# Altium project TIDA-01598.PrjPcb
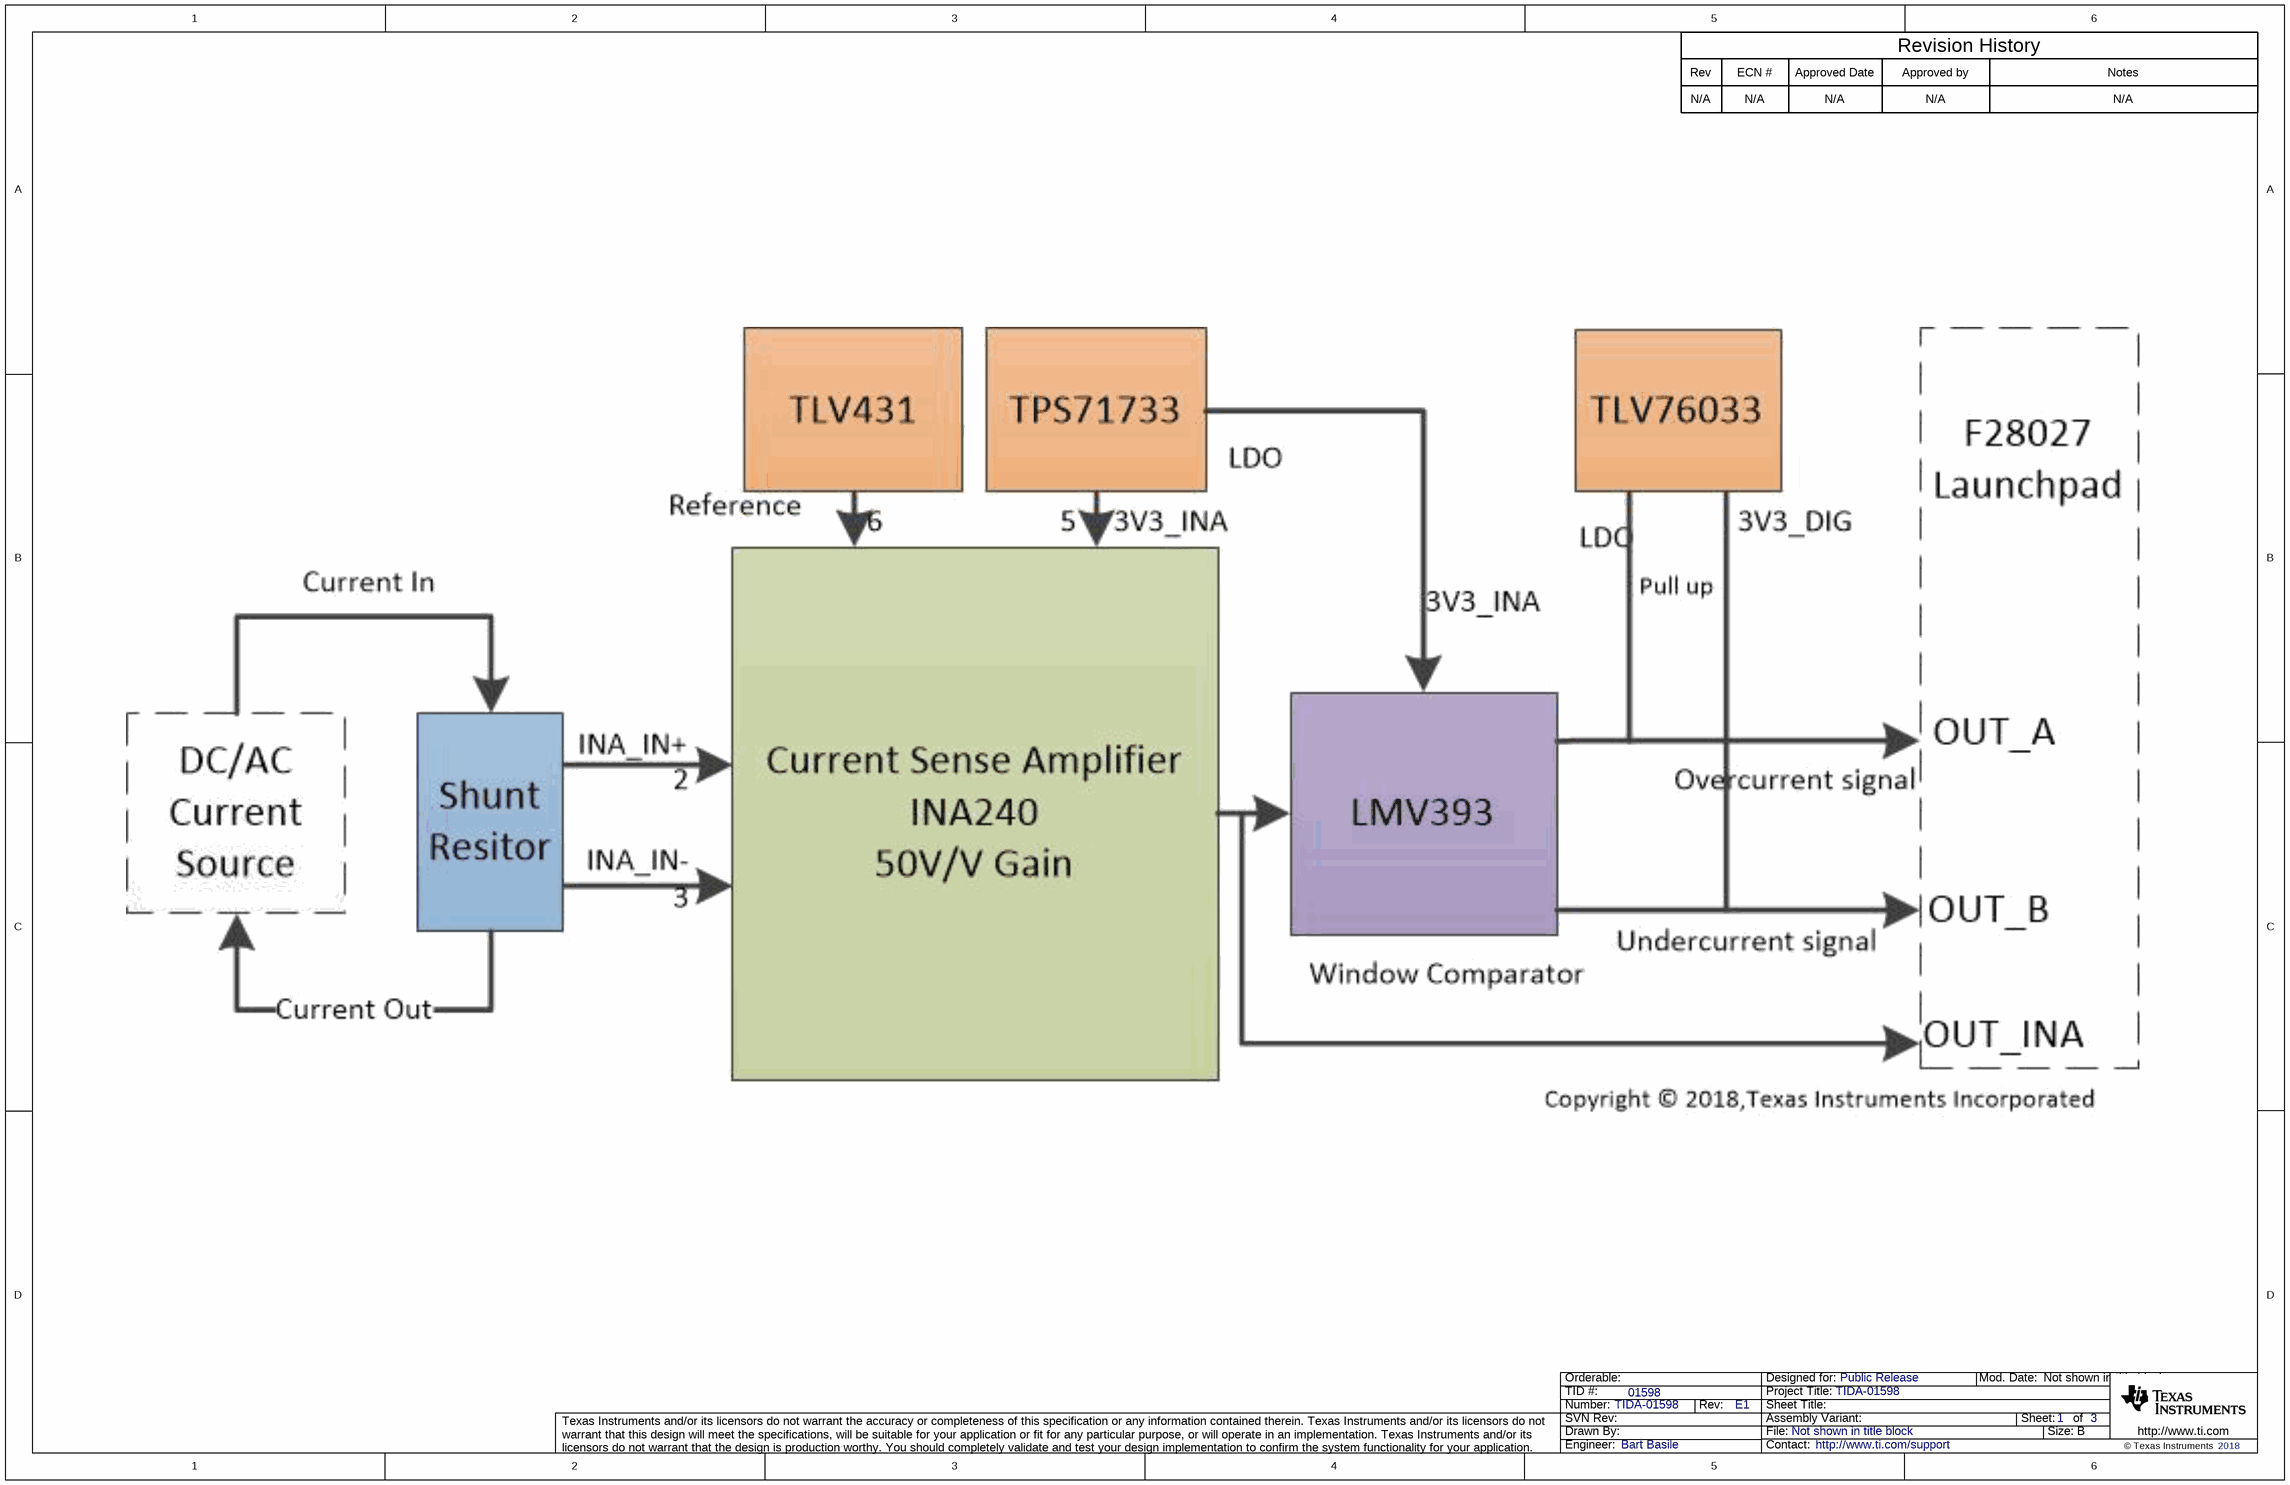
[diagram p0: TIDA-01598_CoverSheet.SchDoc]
CopyrightYear: 2018; PCB_Layout: Avinash N; PCB_Rev: E1; PRJ_Customer: Public Release; PRJ_Engineer: Bart Basile; PRJ_Number: TIDA-01598; PRJ_Title: TIDA-01598; SCH_Rev: E1; TechSupport: http://www.ti.com/support; TID: 01598
4 sheets, 100 parts. Net scope: global (net labels, ports and power ports of the same name join across sheets).
Board file: TIDA-01598_PCB.PcbDoc
Sheets:
  TIDA-01598_CoverSheet.SchDoc
  TIDA-01598_BlankSheet.SchDoc
  TIDA-01598_Main.SchDoc
  TIDA-01598_EVM_Hardware.SchDoc

## Sheet TIDA-01598_CoverSheet.SchDoc
size 431 x 279 mm; Date: Not shown in title block; ApprovedBy: Not shown in title block; CheckedBy: Not shown in title block; Author: Not shown in title block; CompanyName: Not shown in title block; Engineer: Not shown in title block; Organization: Not shown in title block; Address1: Not shown in title block; Address2: Not shown in title block; Address3: Not shown in title block; Address4: Not shown in title block; DocumentNumber: 1; Revision: Use project parameter SCH_Rev; SheetNumber: 1; SheetTotal: 3; PageSetup: Record=PageOptions¦CenterHorizontal=True¦CenterVertical=True¦PrintScale=1.00¦XCorrection=1.00¦YCorrection=1.00¦PrintKind=0¦BorderSize=5000000¦LeftOffset=0¦BottomOffset=0¦Orientation=2¦PaperLength=1000¦PaperWidth=1000¦Scale=100¦PaperSource=15¦PrintQuality=600¦MediaType=1¦DitherType=10¦PaperKind=Letter¦PrintScaleMode=1

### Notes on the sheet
- Rev
- N/A
- ECN #
- Approved Date
- Approved by
- Revision History
- Notes

## Sheet TIDA-01598_BlankSheet.SchDoc
size 431 x 279 mm; Date: Not shown in title block; ApprovedBy: Not shown in title block; CheckedBy: Not shown in title block; Author: Not shown in title block; CompanyName: Not shown in title block; Engineer: Not shown in title block; Organization: Not shown in title block; Address1: Not shown in title block; Address2: Not shown in title block; Address3: Not shown in title block; Address4: Not shown in title block; DocumentNumber: 1; Revision: Use project parameter SCH_Rev; SheetNumber: 2; SheetTotal: 3; PageSetup: Record=PageOptions¦CenterHorizontal=True¦CenterVertical=True¦PrintScale=1.00¦XCorrection=1.00¦YCorrection=1.00¦PrintKind=0¦BorderSize=5000000¦LeftOffset=0¦BottomOffset=0¦Orientation=2¦PaperLength=1000¦PaperWidth=1000¦Scale=100¦PaperSource=15¦PrintQuality=600¦MediaType=1¦DitherType=10¦PaperKind=Letter¦PrintScaleMode=1

## Sheet TIDA-01598_Main.SchDoc
size 431 x 279 mm; Date: Not shown in title block; ApprovedBy: Not shown in title block; CheckedBy: Not shown in title block; Author: Not shown in title block; CompanyName: Not shown in title block; Engineer: Not shown in title block; Organization: Not shown in title block; Address1: Not shown in title block; Address2: Not shown in title block; Address3: Not shown in title block; Address4: Not shown in title block; DocumentNumber: 1; Revision: Use project parameter SCH_Rev; SheetNumber: 2; SheetTotal: 3; PageSetup: Record=PageOptions¦CenterHorizontal=True¦CenterVertical=True¦PrintScale=1.00¦XCorrection=1.00¦YCorrection=1.00¦PrintKind=0¦BorderSize=5000000¦LeftOffset=0¦BottomOffset=0¦Orientation=2¦PaperLength=1000¦PaperWidth=1000¦Scale=100¦PaperSource=15¦PrintQuality=600¦MediaType=1¦DitherType=10¦PaperKind=Letter¦PrintScaleMode=1
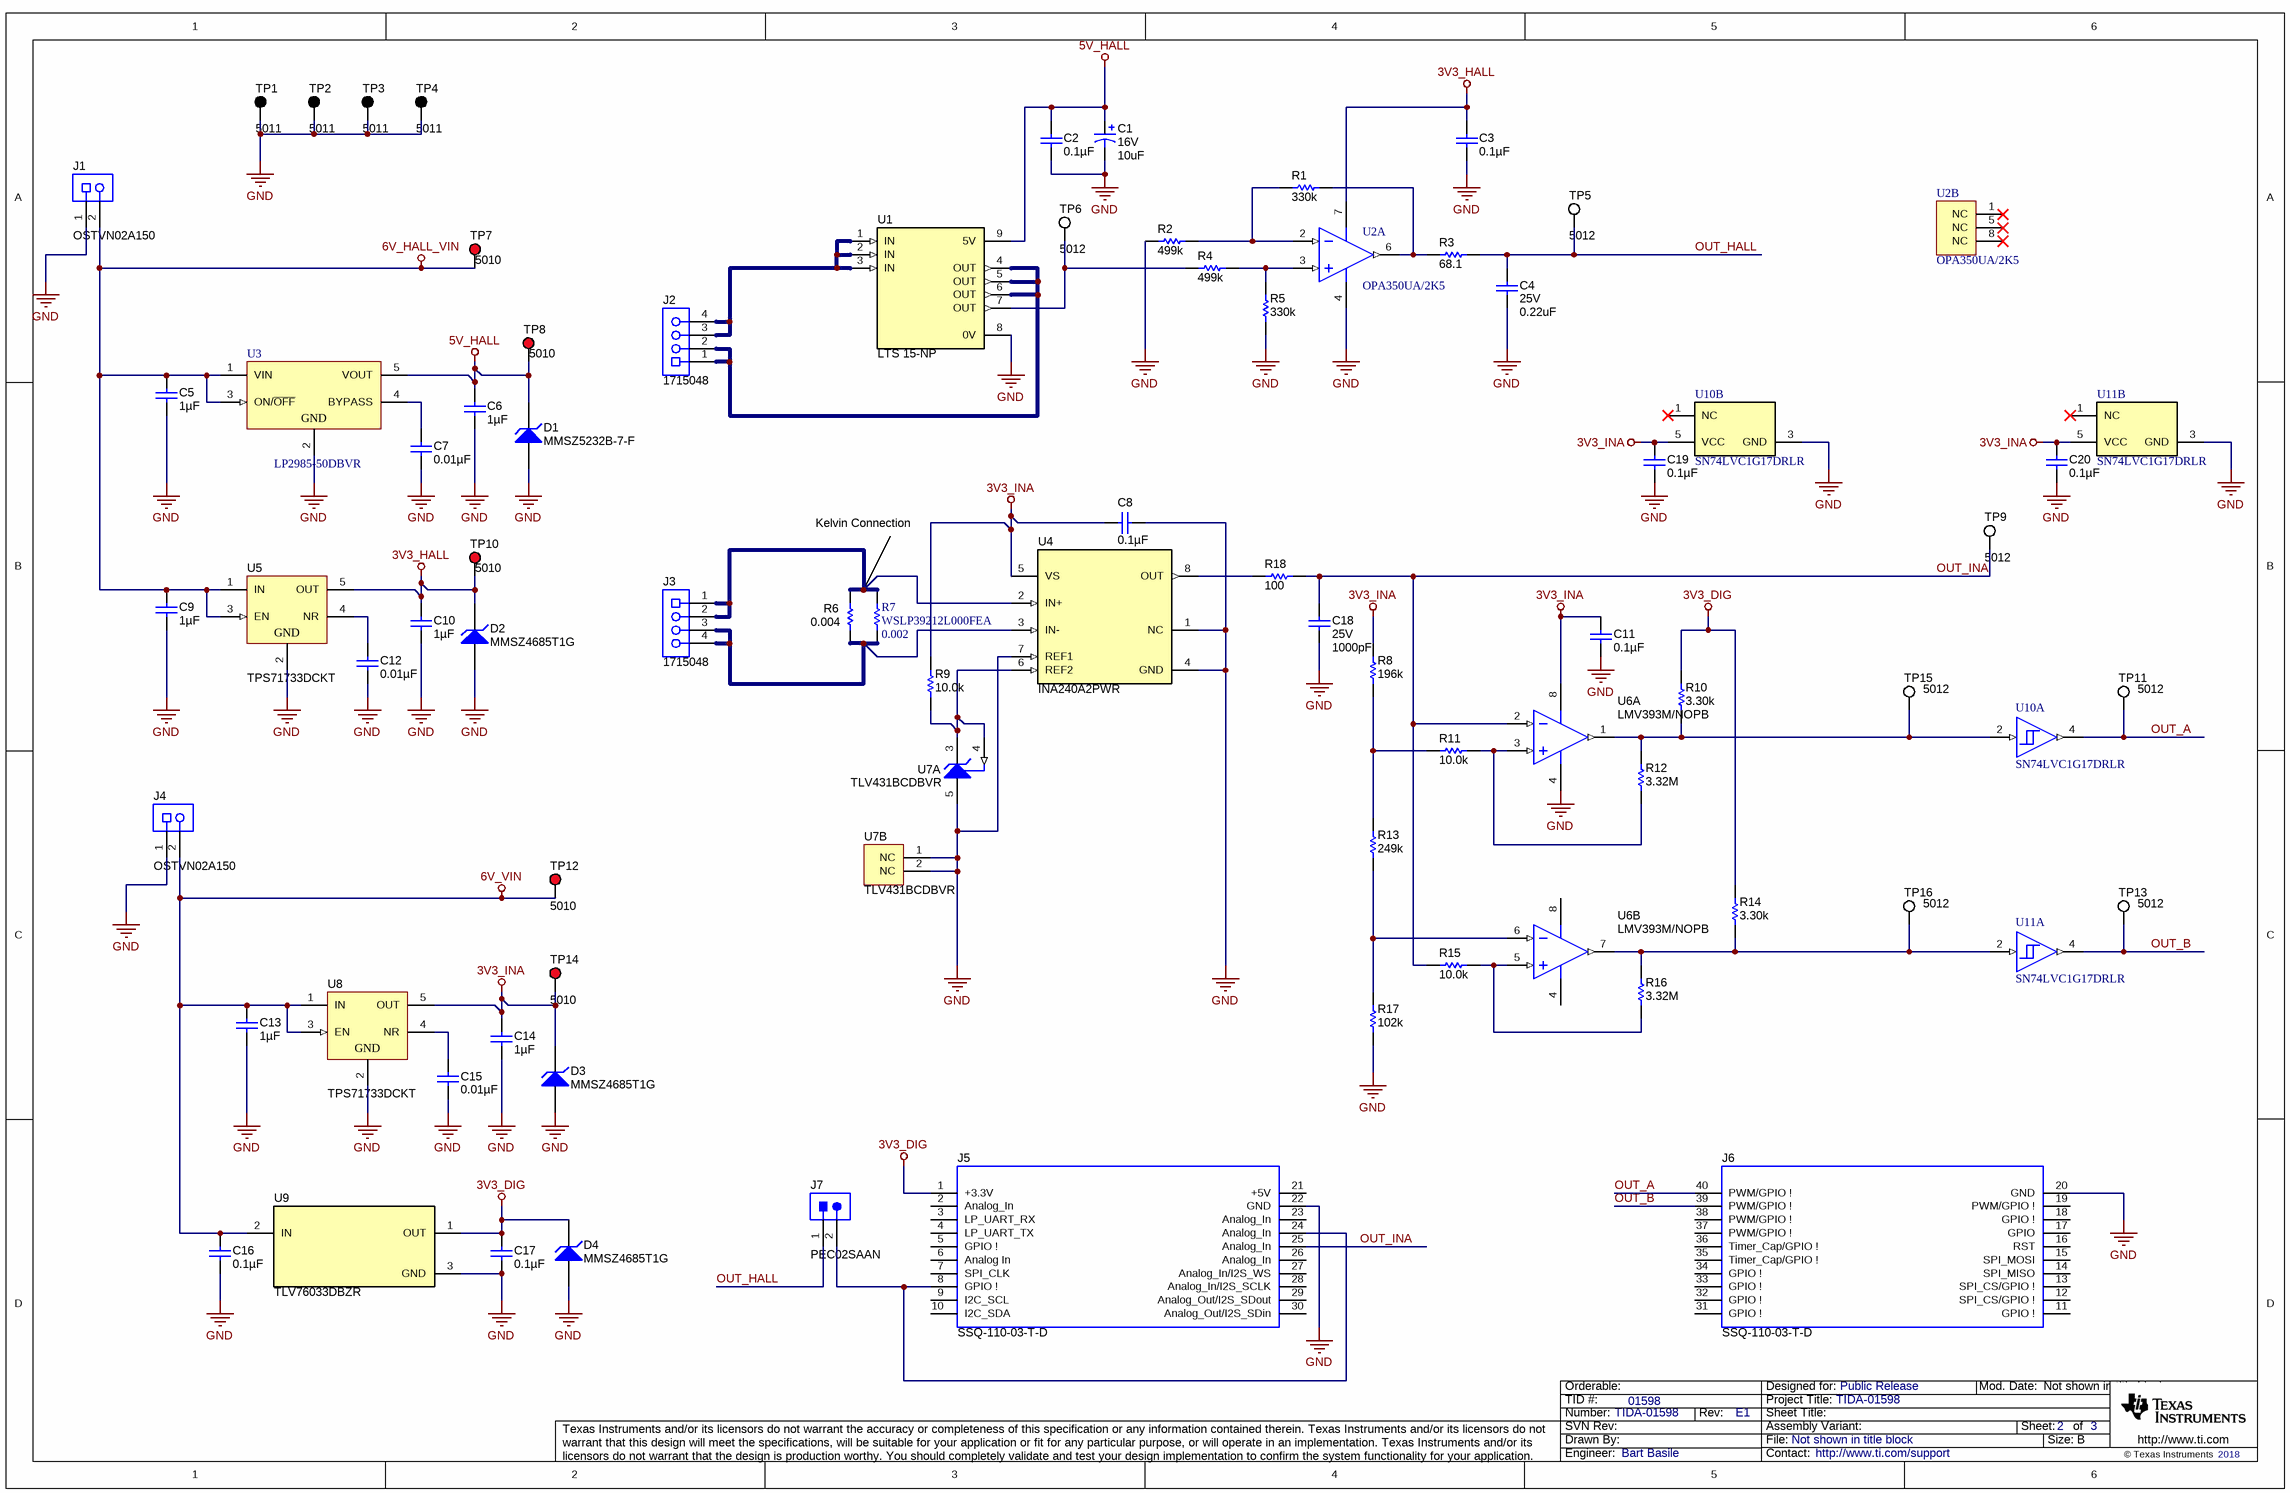
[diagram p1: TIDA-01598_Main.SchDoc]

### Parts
C1  VDC_V: 16V  ValueDisplayed: 10uF  [3528-21]  (hidden comment: TAJB106K016RNJ)
C2  ValueDisplayed: 0.1µF  [0805_HV]  (hidden comment: C0805C104K4RACTU)
C3  ValueDisplayed: 0.1µF  [0402]  (hidden comment: 885012205037)
C4  VDC_V: 25V  ValueDisplayed: 0.22uF  [0603]  (hidden comment: C0603C224J3RAC7867)
C5  ValueDisplayed: 1µF  [0402]  (hidden comment: C1005X5R1E105K050BC)
C6  ValueDisplayed: 1µF  [0402]  (hidden comment: C1005X5R1E105K050BC)
C7  ValueDisplayed: 0.01µF  [0402]  (hidden comment: GRM155R61A103KA01D)
C8  ValueDisplayed: 0.1µF  [0402]  (hidden comment: 885012205037)
C9  ValueDisplayed: 1µF  [0402]  (hidden comment: C1005X5R1E105K050BC)
C10  ValueDisplayed: 1µF  [0402]  (hidden comment: C1005X5R1E105K050BC)
C11  ValueDisplayed: 0.1µF  [0402]  (hidden comment: 885012205037)
C12  ValueDisplayed: 0.01µF  [0402]  (hidden comment: GRM155R61A103KA01D)
C13  ValueDisplayed: 1µF  [0402]  (hidden comment: C1005X5R1E105K050BC)
C14  ValueDisplayed: 1µF  [0402]  (hidden comment: C1005X5R1E105K050BC)
C15  ValueDisplayed: 0.01µF  [0402]  (hidden comment: GRM155R61A103KA01D)
C16  ValueDisplayed: 0.1µF  [0402]  (hidden comment: 885012205037)
C17  ValueDisplayed: 0.1µF  [0402]  (hidden comment: 885012205037)
C18  VDC_V: 25V  ValueDisplayed: 1000pF  [0402]  (hidden comment: C0402C102J3RACTU)
C19  ValueDisplayed: 0.1µF  [0402]  (hidden comment: 885012205037)
C20  ValueDisplayed: 0.1µF  [0402]  (hidden comment: 885012205037)
D1  MMSZ5232B-7-F  [SOD-123]
D2  MMSZ4685T1G  [SOD-123]
D3  MMSZ4685T1G  [SOD-123]
D4  MMSZ4685T1G  [SOD-123]
J1  OSTVN02A150  [On-Shore_OSTVN02A150]
J2  1715048  [Phoenix_1715048]
J3  1715048  [Phoenix_1715048]
J4  OSTVN02A150  [On-Shore_OSTVN02A150]
J5  SSQ-110-03-T-D  [BoosterPack_40pin_J1J3]
J6  SSQ-110-03-T-D  [BoosterPack_40pin_J2J4]
J7  PEC02SAAN  [CONN_PEC02SAAN]
R1  ValueDisplayed: 330k  [0603]  (hidden comment: ERJ-3EKF3303V)
R2  ValueDisplayed: 499k  [0603]  (hidden comment: ERJ-3EKF4993V)
R3  ValueDisplayed: 68.1  [0603]  (hidden comment: CRCW060368R1FKEA)
R4  ValueDisplayed: 499k  [0603]  (hidden comment: ERJ-3EKF4993V)
R5  ValueDisplayed: 330k  [0603]  (hidden comment: ERJ-3EKF3303V)
R6  ValueDisplayed: 0.004  [2010]  (hidden comment: PMR50HZPFV4L00)
R7  WSLP39212L000FEA  value 0.002  [RC3921]
R8  ValueDisplayed: 196k  [0603]  (hidden comment: RT0603BRD07196KL)
R9  ValueDisplayed: 10.0k  [0402]  (hidden comment: CRCW040210K0DHEDP)
R10  ValueDisplayed: 3.30k  [0402]  (hidden comment: ERJ-2RKF3301X)
R11  ValueDisplayed: 10.0k  [0402]  (hidden comment: CRCW040210K0DHEDP)
R12  ValueDisplayed: 3.32M  [0402]  (hidden comment: CRCW04023M32FKED)
R13  ValueDisplayed: 249k  [0603]  (hidden comment: RG1608P-2493-B-T5)
R14  ValueDisplayed: 3.30k  [0402]  (hidden comment: ERJ-2RKF3301X)
R15  ValueDisplayed: 10.0k  [0402]  (hidden comment: CRCW040210K0DHEDP)
R16  ValueDisplayed: 3.32M  [0402]  (hidden comment: CRCW04023M32FKED)
R17  ValueDisplayed: 102k  [0603]  (hidden comment: RT0603BRD07102KL)
R18  ValueDisplayed: 100  [0402]  (hidden comment: RC0402FR-07100RL)
TP1  5011  [Keystone5011]
TP2  5011  [Keystone5011]
TP3  5011  [Keystone5011]
TP4  5011  [Keystone5011]
TP5  5012  [Keystone5012]
TP6  5012  [Keystone5012]
TP7  5010  [Keystone5010]
TP8  5010  [Keystone5010]
TP9  5012  [Keystone5012]
TP10  5010  [Keystone5010]
TP11  5012  [Keystone5012]
TP12  5010  [Keystone5010]
TP13  5012  [Keystone5012]
TP14  5010  [Keystone5010]
TP15  5012  [Keystone5012]
TP16  5012  [Keystone5012]
U1  LTS 15-NP  [LEM_LTS]
U2  OPA350UA/2K5  [D0008A_L]  (parts A,B of 2)
U3  LP2985-50DBVR  [DBV0005A_N]
U4  INA240A2PWR  [PW0008A_L]
U5  TPS71733DCKT  [DCK0005A_N]
U6  LMV393M/NOPB  [D0008A_N]  (parts A,B of 2)
U7  TLV431BCDBVR  [DBV0005A_N]  (parts A,B of 2)
U8  TPS71733DCKT  [DCK0005A_N]
U9  TLV76033DBZR  [DBZ0003A_N]
U10  SN74LVC1G17DRLR  [DRL0005A]  (parts A,B of 2)
U11  SN74LVC1G17DRLR  [DRL0005A]  (parts A,B of 2)

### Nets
3V3_DIG: C17.1 D4.1(K) J5.1(+3.3V) R10.2 R14.2 U9.1(OUT)
3V3_HALL: C3.1 C10.1 D2.1(K) TP10.1 U2.7(V+) U5.5(OUT)
3V3_INA: C8.1 C11.1 C14.1 C19.1 C20.1 D3.1(K) R8.2 R9.2 TP14.1 U4.5(VS) U6.8(V+) U8.5(OUT) U10.5(VCC) U11.5(VCC)
5V_HALL: C1.1(+) C2.1 C6.1 D1.1(K) TP8.1 U1.9(5V) U3.5(VOUT)
6V_HALL_VIN: C5.1 C9.1 J1.2 TP7.1 U3.1(VIN) U3.3(ON/~{OFF}) U5.1(IN) U5.3(EN)
6V_VIN: C13.1 C16.1 J4.2 TP12.1 U8.1(IN) U8.3(EN) U9.2(IN)
GND: C1.2(-) C2.2 C3.2 C4.2 C5.2 C6.2 C7.2 C8.2 C9.2 C10.2 C11.2 C12.2 C13.2 C14.2 C15.2 C16.2 C17.2 C18.2 C19.2 C20.2 D1.2(A) D2.2(A) D3.2(A) D4.2(A) J1.1 J4.1 J5.22(GND) J6.20(GND) R2.1 R5.1 R17.2 TP1.1 TP2.1 TP3.1 TP4.1 U1.8(0V) U2.4(V-) U3.2(GND) U4.1(NC) U4.4(GND) U4.7(REF1) U5.2(GND) U6.4(V-) U7.1(NC) U7.2(NC) U7.5(ANODE) U8.2(GND) U9.3(GND) U10.3(GND) U11.3(GND)
OUT_A: J6.40(PWM/GPIO_!) TP11.1 U10.4(Y)
OUT_B: J6.39(PWM/GPIO_!) TP13.1 U11.4(Y)
OUT_HALL: C4.1 J7.1 R3.2 TP5.1
OUT_INA: C18.1 J5.25(Analog_In) R15.1 R18.2 TP9.1 U6.2(INA-)
NetC7_1: C7.1 U3.4(BYPASS)
NetC12_1: C12.1 U5.4(NR)
NetC15_1: C15.1 U8.4(NR)
NetJ2_1: J2.1 J2.2 U1.4(OUT) U1.5(OUT) U1.6(OUT)
NetJ2_3: J2.3 J2.4 U1.1(IN) U1.2(IN) U1.3(IN)
NetJ3_1: J3.1 J3.2 R6.2 R7.2 U4.2(IN+)
NetJ3_3: J3.3 J3.4 R6.1 R7.1 U4.3(IN-)
NetJ5_8: J5.8(GPIO_!) J5.24(Analog_In) J7.2
NetR1_1: R1.1 R2.2 U2.2(IN-)
NetR1_2: R1.2 R3.1 U2.6(OUT)
NetR4_1: R4.1 TP6.1 U1.7(OUT)
NetR4_2: R4.2 R5.2 U2.3(IN+)
NetR8_1: R8.1 R11.1 R13.2
NetR9_1: R9.1 U4.6(REF2) U7.3(CATHODE) U7.4(REF)
NetR10_1: R10.1 R12.2 TP15.1 U6.1(OUTA) U10.2(A)
NetR11_2: R11.2 R12.1 U6.3(INA+)
NetR13_1: R13.1 R17.1 U6.6(INB-)
NetR14_1: R14.1 R16.2 TP16.1 U6.7(OUTB) U11.2(A)
NetR15_2: R15.2 R16.1 U6.5(INB+)
NetR18_1: R18.1 U4.8(OUT)

Not connected (* = marked no-connect by the designer): J5 2(Analog_In) 3(LP_UART_RX) 4(LP_UART_TX) 5(GPIO_!) 6(Analog_In) 7(SPI_CLK) 9(I2C_SCL) 10(I2C_SDA) 21(+5V) 23(Analog_In) 26(Analog_In) 27(Analog_In/I2S_WS) 28(Analog_In/I2S_SCLK) 29(Analog_Out/I2S_SDout) 30(Analog_Out/I2S_SDin); J6 11(GPIO_!) 12(SPI_CS/GPIO_!) 13(SPI_CS/GPIO_!) 14(SPI_MISO) 15(SPI_MOSI) 16(RST) 17(GPIO) 18(GPIO_!) 19(PWM/GPIO_!) 31(GPIO_!) 32(GPIO_!) 33(GPIO_!) 34(GPIO_!) 35(Timer_Cap/GPIO_!) 36(Timer_Cap/GPIO_!) 37(PWM/GPIO_!) 38(PWM/GPIO_!); U2 1(NC)* 5(NC)* 8(NC)*; U10 1(NC)*; U11 1(NC)*

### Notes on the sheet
- Kelvin Connection

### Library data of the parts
C1 = CMP-0011561-2: CAP, TA, 10 uF, 16 V, +/- 10%, 2.8 ohm, SMD; Manufacturer: AVX; TaMin_C: -55°C; ESR_ohm: 2.8; Polarized: Y; SizeAreaWB_mm2: 17.1; Value1: 2.8 ohm; U/M: EA; Value: 10uF; TaMax_C: 125°C; SizeZ_mm: 2.1; SizeX_mm: 3.5; SizeArea_mm2: 9.8; CompType: Capacitor; AEC Qualified: N; Cap_F: 10µF; IRMS_A: 1.74dA; AEC Category: Q200
C2 = C0805C104K4RACTU: CAP, CERM, 0.1 µF, 16 V,+/- 10%, X7R, 0805; Manufacturer: Kemet; Polarized: N; CompType: Capacitor; Value: 0.1uF; U/M: EA; Cap_F: 0.0000001; Tolerance_%: 10; ESR_ohm: 0.064; Value1: 0.064 ohm; VDC_V: 16; Value2: 16V; IRMS_A: 1.64; TaMin_C: -55; TaMax_C: 125; Cap_Case: 0805; SizeArea_mm2: 2.5; SizeAreaWB_mm2: 6.75; SizeX_mm: 2; SizeY_mm: 1.25; SizeZ_mm: 1.45; AEC Category: Q200; Green_Lifecycle: Active; Green_REACh: Passed
C3 C8 C11 C16 C17 C19 C20 = 885012205037: CAP, CERM, 0.1 µF, 16 V,+/- 10%, X7R, 0402; Manufacturer: Wurth Elektronik; Polarized: N; CompType: Capacitor; Value: 0.1uF; U/M: EA; Cap_F: 0.0000001; Tolerance_%: 10; VDC_V: 16; Value2: 16V; TaMin_C: -55; TaMax_C: 125; SizeArea_mm2: 0.5; SizeAreaWB_mm2: 3; SizeX_mm: 1; SizeZ_mm: 0.6; AEC Category: Q200; Green_Lifecycle: Active; Green_REACh: Passed
C4 = CMP-0006902-5: CAP, CERM, 0.22 uF, 25 V, +/- 5%, X7R, 0603; Manufacturer: Kemet; TaMin_C: -55°C; Polarized: N; SizeAreaWB_mm2: 4.68; Value1: Unknown; U/M: EA; Value: 0.22uF; TaMax_C: 125°C; SizeZ_mm: 1; SizeX_mm: 1.6; SizeY_mm: 0.8; SizeArea_mm2: 1.28; Cap_F: 220nF; AEC Category: Q200
C5 C6 C9 C10 C13 C14 = C1005X5R1E105K050BC: CAP, CERM, 1 µF, 25 V,+/- 10%, X5R, 0402; Manufacturer: TDK; Polarized: N; CompType: Capacitor; Value: 1uF; U/M: EA; Cap_F: 0.000001; Tolerance_%: 10; VDC_V: 25; Value2: 25V; TaMin_C: -55; TaMax_C: 80; SizeArea_mm2: 0.5; SizeAreaWB_mm2: 3; SizeX_mm: 1; SizeZ_mm: 0.6; AEC Category: Q200; Green_Lifecycle: Active; Green_REACh: Passed
C7 C12 C15 = GRM155R61A103KA01D: CAP, CERM, 0.01 µF, 10 V,+/- 10%, X5R, 0402; Manufacturer: MuRata; Polarized: N; CompType: Capacitor; Value: 0.01uF; U/M: EA; Cap_F: 0.00000001; Tolerance_%: 10; Value2: 10V; TaMin_C: -55; TaMax_C: 85; SizeArea_mm2: 0.5; SizeAreaWB_mm2: 3; SizeX_mm: 1; SizeZ_mm: 0.6; AEC Category: Q200; Green_Lifecycle: Active; Green_REACh: Passed
C18 = CMP-0006234-2: CAP, CERM, 1000 pF, 25 V, +/- 5%, X7R, 0402; Manufacturer: Kemet; TaMin_C: -55°C; Polarized: N; SizeAreaWB_mm2: 3; Value1: Unknown; U/M: EA; Value: 1000pF; TaMax_C: 125°C; SizeZ_mm: 0.6; SizeX_mm: 1; SizeY_mm: 0.5; Cap_F: 1nF; AEC Category: Q200
D1 = CMP-0005803-1: Diode, Zener, 5.6 V, 500 mW, SOD-123; Manufacturer: Diodes Inc.; Power_W: 500mW; SizeAreaWB_mm2: 13.095; Vz_V: 5.6V; Value1: 0.5W; RJA_CperW: 350; U/M: EA; Value: 5.6V; SizeZ_mm: 1.35; SizeX_mm: 3.85; SizeY_mm: 1.7; SizeArea_mm2: 6.545; AEC Category: Q101
D2-D4 = CMP-0005782-1: Diode, Zener, 3.6 V, 500 mW, SOD-123; Manufacturer: ON Semiconductor; Power_W: 500mW; SizeAreaWB_mm2: 13.095; Vz_V: 3.6V; Value1: 0.5W; RJA_CperW: 340; U/M: EA; Value: 3.6V; SizeZ_mm: 1.35; SizeX_mm: 3.85; SizeY_mm: 1.7; SizeArea_mm2: 6.545; AEC Category: Q101
J1 J4 = CMP-0075076-1: Terminal Block, 2.54mm, 2x1, Brass, TH; Manufacturer: On-Shore Technology; CT: True; Green_REACh: Incomplete; CNHeader: False; Green_Lifecycle: Not Set
J2 J3 = CMP-0055526-1: Terminal Block, 5mm, 4x1, R/A,TH; Manufacturer: Phoenix Contact; Cert_VDE: Y; CNHeader: FALSE; Current_A: 17.5A; Gender: Female; Voltage_V: 400V; Row_Count: 1; Pitch_mm: 5; CT: TRUE
J5 = CMP-0003837-1: Receptacle, 2.54mm, 10x2, Tin, TH; Alternate PartNumber: CRD-081413-A-G; Manufacturer: Samtec; Alternate Manufacturer: Major League Electronics; Note: Booster Pack 40 pin J1 and J3
J6 = CMP-0078266-1: Receptacle, 2.54mm, 10x2, Tin, TH; Alternate PartNumber: CRD-081413-A-G; Manufacturer: Samtec; Alternate Manufacturer: Major League Electronics; Note: Booster Pack 40 pin J2 and J4; Green_REACh: Passed; Green_Lifecycle: Active
J7 = CMP-0002337-1: Header, 100mil, 2x1, Tin, TH; Manufacturer: Sullins Connector Solutions; CNHeader: TRUE; Current_A: 3A; Green_Lifecycle: Not Set; Shrouded: N; Gender: Male; Green_REACh: Incomplete; Voltage_V: 1.8kV; Row_Count: 1; Pitch_mm: 2.54; CT: FALSE; Cert_UL: Y
R1 R5 = CMP-0022697-2: RES, 330 k, 1%, 0.1 W, AEC-Q200 Grade 0, 0603; Manufacturer: Panasonic; Power_W: 100mW; TempCo: 100 ppm/C; U/M: EA; Value: 330k; SizeX_mm: 1.6; SizeY_mm: 0.8; SizeZ_mm: 1; Value2: 0.1W; SizeArea_mm2: 1.28; AEC Qualified: Y; VDC_V: 75V; AEC Grade: 0; AEC Category: Q200
R2 R4 = CMP-0022706-2: RES, 499 k, 1%, 0.1 W, AEC-Q200 Grade 0, 0603; Manufacturer: Panasonic; Power_W: 100mW; TempCo: 100 ppm/C; U/M: EA; Value: 499k; EIA_Code: E96; SizeX_mm: 1.6; SizeY_mm: 0.8; SizeZ_mm: 1; Value2: 0.1W; SizeArea_mm2: 1.28; AEC Qualified: Y; VDC_V: 75V; AEC Grade: 0; AEC Category: Q200
R3 = CMP-0022553-3: RES, 68.1, 1%, 0.1 W, 0603; Manufacturer: Vishay-Dale; Power_W: 100mW; TempCo: 100 ppm/C; Value_Code: 68R1; U/M: EA; Value: 68.1; EIA_Code: E96; SizeX_mm: 1.6; SizeY_mm: 0.8; SizeZ_mm: 1; Value2: 0.1W; SizeArea_mm2: 1.28; VDC_V: 75V; AEC Category: Q200
R6 = CMP-0016545-2: RES, 0.004, 1%, 1 W, 2010; Manufacturer: Rohm; Power_W: 1W; TempCo: 100 ppm/C; Value_Code: 4L000; U/M: EA; Value: 0.004; Res_ohm: 4m; SizeX_mm: 5; SizeY_mm: 2.5; SizeZ_mm: 1.66; SizeArea_mm2: 12.5; AEC Category: Q200
R7 = WSLP39213L000FEB: RES 0.002 OHM 1% 5W 3921; Manufacturer: VISHAY DALE; CompType: RESISTOR; SymbolCreator: x0199378
R8 = CMP-0023850-3: RES, 196 k, 0.1%, 0.1 W, 0603; Manufacturer: Yageo America; Power_W: 100mW; TempCo: 25 ppm/C; U/M: EA; Value: 196k; EIA_Code: E192; SizeX_mm: 1.6; SizeY_mm: 0.8; SizeZ_mm: 1; Value2: 0.1W; SizeArea_mm2: 1.28; VDC_V: 75V; AEC Category: Q200
R9 R11 R15 = CRCW040210K0DHEDP: RES, 10.0 k, 0.5%, 0.063 W, 0402; Manufacturer: Vishay-Dale; CompType: Resistor; Value: 10.0k; Res_ohm: 10000; Value_Code: 10k0; Tolerance_%: 0.5; Power_W: 0.063; Value2: 0.063W; VDC_V: 50; TempCo: 50 ppm/C; SizeX_mm: 1; SizeZ_mm: 0.6; EIA_Code: E192; U/M: EA; AEC Category: Q200
R10 R14 = ERJ-2RKF3301X: RES, 3.30 k, 1%, 0.1 W, AEC-Q200 Grade 0, 0402; Manufacturer: Panasonic; CompType: Resistor; Value: 3.30k; Res_ohm: 3300; Value_Code: 3k30; Tolerance_%: 1; Power_W: 0.1; Value2: 0.1W; VDC_V: 50; TempCo: 100 ppm/C; SizeArea_mm2: 0.5; SizeZ_mm: 0.6; U/M: EA; AEC Category: Q200; AEC Qualified: Y; AEC Grade: 0
R12 R16 = CRCW04023M32FKED: RES, 3.32 M, 1%, 0.063 W, 0402; Manufacturer: Vishay-Dale; CompType: Resistor; Value: 3.32Meg; Res_ohm: 3320000; Value_Code: 3M32; Tolerance_%: 1; Power_W: 0.063; Value2: 0.063W; VDC_V: 50; TempCo: 100 ppm/C; SizeArea_mm2: 0.5; SizeZ_mm: 0.6; EIA_Code: E96; U/M: EA; AEC Category: Q200
R13 = CMP-0023490-3: RES, 249 k, 0.1%, 0.1 W, 0603; Manufacturer: Susumu Co Ltd; Power_W: 100mW; TempCo: 25 ppm/C; U/M: EA; Value: 249k; EIA_Code: E192; SizeX_mm: 1.6; SizeY_mm: 0.8; SizeZ_mm: 1; Value2: 0.1W; SizeArea_mm2: 1.28; VDC_V: 75V; AEC Category: Q200
R17 = CMP-0023634-3: RES, 102 k, 0.1%, 0.1 W, 0603; Manufacturer: Yageo America; Power_W: 100mW; TempCo: 25 ppm/C; U/M: EA; Value: 102k; EIA_Code: E192; SizeX_mm: 1.6; SizeY_mm: 0.8; SizeZ_mm: 1; Value2: 0.1W; SizeArea_mm2: 1.28; VDC_V: 75V; AEC Category: Q200
R18 = CMP-0026722-1: RES, 100, 1%, 0.063 W, 0402; Manufacturer: Yageo America; Power_W: 63mW; TempCo: 100 ppm/C; Value_Code: 100R; U/M: EA; Value: 100; EIA_Code: E96; SizeX_mm: 1; SizeY_mm: 0.5; SizeZ_mm: 0.6; Value2: 0.063W; AEC Qualified: N; VDC_V: 50V; AEC Category: Q200
TP1-TP4 = CMP-0055148-1: Test Point, Multipurpose, Black, TH; Manufacturer: Keystone; CNHeader: FALSE; Green_Lifecycle: Active; Green_REACh: Passed; ContactFinish: Silver; CT: TRUE
TP5 TP6 TP9 TP11 TP13 TP15 TP16 = CMP-0055149-1: Test Point, Multipurpose, White, TH; Manufacturer: Keystone; CNHeader: FALSE; Green_Lifecycle: Active; Green_REACh: Passed; ContactFinish: Silver; CT: TRUE
TP7 TP8 TP10 TP12 TP14 = CMP-0055147-1: Test Point, Multipurpose, Red, TH; Manufacturer: Keystone; CNHeader: FALSE; Green_Lifecycle: Active; Green_REACh: Passed; ContactFinish: Silver; CT: TRUE
U1 = CMP-0078305-1: Current Transducer, TH; Manufacturer: LEM; SizeAreaWB_mm2: 375.1; SizeArea_mm2: 299.7; SizeZ_mm: 24.2; SizeY_mm: 13.5; SizeX_mm: 22.2
U2 = CMP-0040981-2: High-Speed, Single-Supply, Rail-to-Rail Operational Amplifier MicroAmplifier(TM) Series, 2.7 to 5.5 V, -40 to 85 degC, 8-pin SOIC (D8), Green (RoHS & no Sb/Br); Manufacturer: Texas Instruments; Sub Family: Low Input Bias Current Amp (<=10pA), Low Offset Voltage Amplifier (<=500uV), Low Supply Voltage Amplifier (<=2.7V), Precision Amplifier; Total Supply Voltage(Min)(+5V is 5, +/-5V is 10): 2.7; Slew Rate(Typ)(V/us): 22; Vio (25C)(Max)(mV): 1; Total Supply Voltage(Max)(+5V is 5, +/-5V is 10): 5.5; IIB(Max)(pA): 10; Offset Drift(Typ)(uV/C): 4; Iq per channel(Max)(mA): 8.5; CMRR(Min)(dB): 66; Vn at 1kHz(Typ)(nV/rtHz): 18
U3 = CMP-0036298-1: Single Output Low Noise LDO, 150 mA, Fixed 5 V Output, 1.5% Tolerance, 2.2 to 16 V Input, Low IQ, 5-Pin SOT-23 (DBV), -40 to 125 degC, Green (RoHS & no Sb/Br), Tape and Reel; Manufacturer: Texas Instruments; Vdo (Typ) (mV): 280; Iout (Max) (A): 0.15; Accuracy (%): 1.5; Fixed Output Options (V): 5; Iq (Typ) (mA): 0.85; Output Options: Fixed Output
U4 = CMP-0075735-1: High/Low Side, Bi-Directional Zero-Drift Current Sense Amp w/ Enhanced PWM Rejection, PW0008A (TSSOP-8); Alternate Manufacturer: Texas Instruments; SizeX_mm: 6.4; CompType: IC; SizeAreaWB_mm2: 42.0; SizeZ_mm: 1.2; SizeY_mm: 3.0; U/M: EA; SizeArea_mm2: 19.2
U5 U8 = CMP-0035674-1: Single Output High PSRR LDO, 150 mA, Fixed 3.3 V Output, 2.5 to 6.5 V Input, with Low IQ, 5-pin SC70 (DCK), -40 to 85 degC, Green (RoHS & no Sb/Br); Manufacturer: Texas Instruments; Fixed Output Options(V): 3.3; Vin(Min)(V): 2.5; SubFamily: Single Channel LDO; Iq(Typ)(mA): 0.05; Vdo(Typ)(mV): 170; Accuracy(%): 3; Vin(Max)(V): 6.5; Iout(Max)(A): 0.15
U6 = CMP-0068190-2: Dual General Purpose, Low Voltage, Tiny Pack Comparator, 8-pin Narrow SOIC, Pb-Free; Manufacturer: Texas Instruments; CompType: IC; AEC Category: Q200; AEC Qualified: N; SizeAreaWB_mm2: 56.58; SizeArea_mm2: 30.38; SizeX_mm: 4.9; SizeY_mm: 6.2; SizeZ_mm: 1.75
U7 = CMP-0032938-1: Low-Voltage Adjustable Precision Shunt Regulator, 15 mA, 0 to 70 degC, 5-pin SOT-23 (DBV), Green (RoHS & no Sb/Br); Manufacturer: Texas Instruments; SubFamily: Shunt Voltage Reference; Temp Coeff(Max)(ppm/ degree C): 129; VO Adj(Min)(V): 1.24; VO Adj(Max)(V): 6; Iout/Iz(Max)(mA): 15; Rating: Catalog; Min Iz for Regulation(uA): 80; Initial Accuracy @ 25/deg C(%): 0.5
U9 = CMP-0074893-1: 100-mA, 30-V, Fixed-Output, Linear-Voltage Regulator, DBZ0003A (SOT-23-3); Alternate PartNumber: TLV76033DBZT; Alternate Manufacturer: Texas Instruments; SizeAreaWB_mm2: 14.0; SizeZ_mm: 1.12; SizeX_mm: 2.5; SizeY_mm: 3.0; SizeArea_mm2: 7.5; CompType: IC; AEC Qualified: N; AEC Category: Q200
U10 U11 = CMP-0051707-3: Single Schmitt-Trigger Buffer, DRL0005A, LARGE T&R; Manufacturer: Texas Instruments; Voltage(Nom)(V): 1.8,2.5,3.3,5; Schmitt Trigger: Yes; 3-State Output: No; ICC @ Nom Voltage(Max)(mA): 0.01; Input Type: CMOS/TTL; Output Type: CMOS; F @ Nom Voltage(Max)(Mhz): 150; Sub-Family: Non-Inverting Buffer/Driver; VCC(Min)(V): 1.65; Technology Family: LVC; Output Drive (IOL/IOH)(Max)(mA): 32/-32; VCC(Max)(V): 5.5; Logic: True; Bits(#): 1; Rating: Catalog; tpd @ Nom Voltage(Max)(ns): 11,6.5,5.5,5; AEC Category: Q200; AEC Qualified: N; CompType: IC; SizeX_mm: 1.6; SizeZ_mm: 0.6

## Sheet TIDA-01598_EVM_Hardware.SchDoc
size 431 x 279 mm; Date: Not shown in title block; ApprovedBy: Not shown in title block; CheckedBy: Not shown in title block; Author: Not shown in title block; CompanyName: Not shown in title block; Engineer: Not shown in title block; Organization: Not shown in title block; Address1: Not shown in title block; Address2: Not shown in title block; Address3: Not shown in title block; Address4: Not shown in title block; DocumentNumber: 1; Revision: Use project parameter SCH_Rev; SheetNumber: 3; SheetTotal: 3; PageSetup: Record=PageOptions¦CenterHorizontal=True¦CenterVertical=True¦PrintScale=1.00¦XCorrection=1.00¦YCorrection=1.00¦PrintKind=0¦BorderSize=5000000¦LeftOffset=0¦BottomOffset=0¦Orientation=2¦PaperLength=1000¦PaperWidth=1000¦Scale=100¦PaperSource=15¦PrintQuality=600¦MediaType=1¦DitherType=10¦PaperKind=Letter¦PrintScaleMode=1
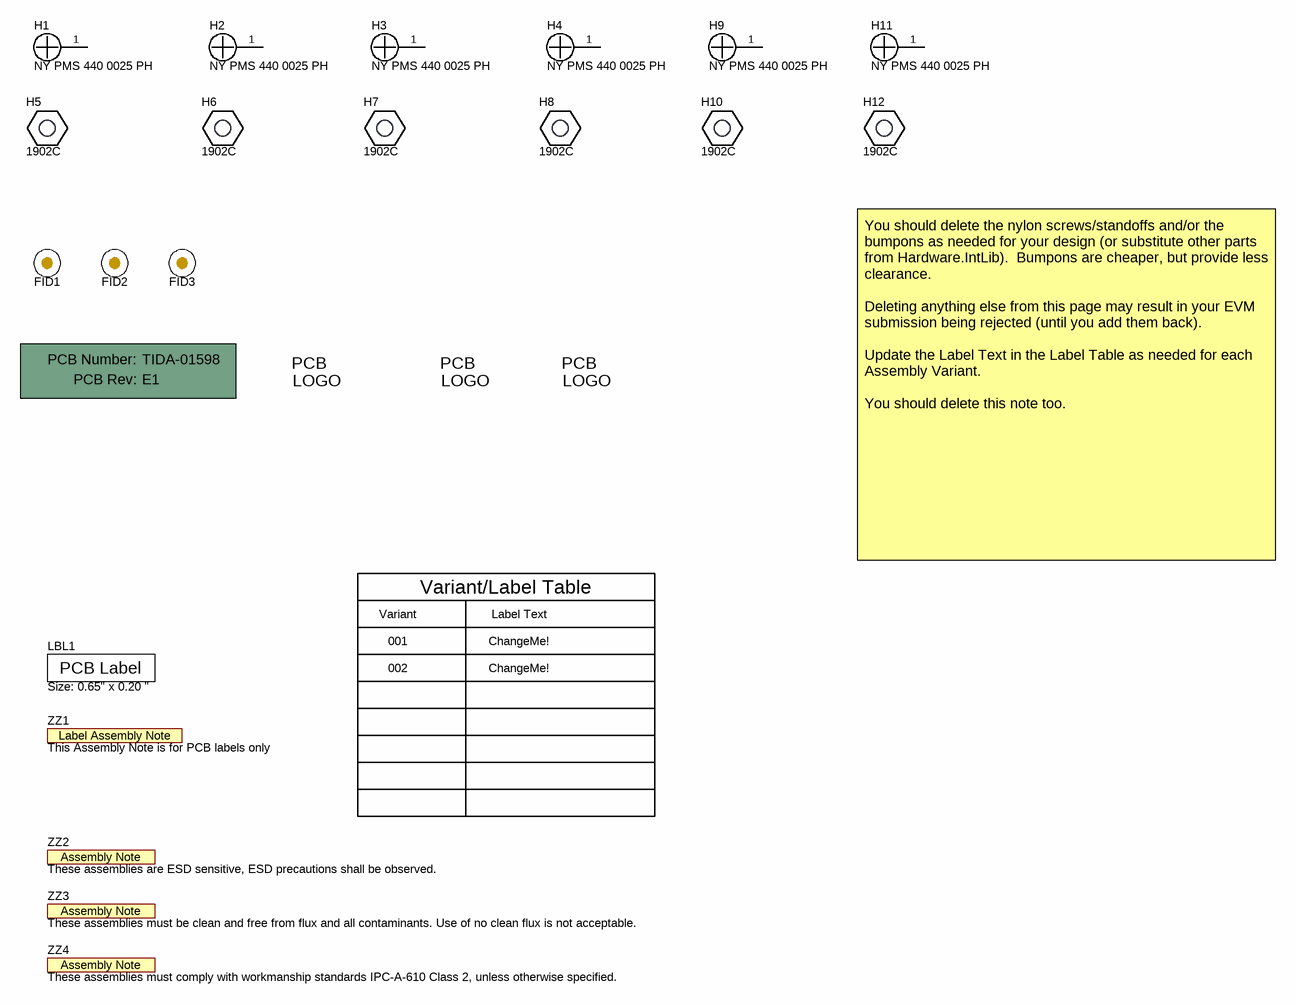
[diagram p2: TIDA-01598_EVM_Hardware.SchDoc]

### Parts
!PCB1  Printed Circuit Board  (value not drawn)  (mechanical)
FID1  Fiducial  [Fiducial10-20]  (value not drawn)
FID2  Fiducial  [Fiducial10-20]  (value not drawn)
FID3  Fiducial  [Fiducial10-20]  (value not drawn)
H1  NY PMS 440 0025 PH  [NY PMS 440 0025 PH]
H2  NY PMS 440 0025 PH  [NY PMS 440 0025 PH]
H3  NY PMS 440 0025 PH  [NY PMS 440 0025 PH]
H4  NY PMS 440 0025 PH  [NY PMS 440 0025 PH]
H5  1902C  [Keystone_1902C]
H6  1902C  [Keystone_1902C]
H7  1902C  [Keystone_1902C]
H8  1902C  [Keystone_1902C]
H9  NY PMS 440 0025 PH  [NY PMS 440 0025 PH]
H10  1902C  [Keystone_1902C]
H11  NY PMS 440 0025 PH  [NY PMS 440 0025 PH]
H12  1902C  [Keystone_1902C]
LBL1  Size: 0.65" x 0.20 "  [Label_650x200]
Logo1  Texas Instruments  [TI_Stacked_Overlay_Small]  (value not drawn)  (no BOM)
Logo2  Pb-Free Symbol  [Pb-Free_Overlay_Small]  (value not drawn)  (no BOM)
Logo3  FCC disclaimer  [FCC_disclaimer]  (value not drawn)  (no BOM)
ZZ1  This Assembly Note is for PCB labels only  [AssemblyNoteLabel]  (no BOM)
ZZ2  These assemblies are ESD sensitive, ESD precautions shall be observed.  [AssemblyNote]  (no BOM)
ZZ3  These assemblies must be clean and free from flux and all contaminants. Use of no clean flux is not acceptable.  [AssemblyNote]  (no BOM)
ZZ4  These assemblies must comply with workmanship standards IPC-A-610 Class 2, unless otherwise specified.  [AssemblyNote]  (no BOM)

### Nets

Not connected (* = marked no-connect by the designer): H1 1; H2 1; H3 1; H4 1; H9 1; H11 1

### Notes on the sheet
- Variant
- Variant/Label Table
- Label Text
- You should delete the nylon screws/standoffs and/or the bumpons as needed for your design (or substitute other parts from Hardware.IntLib).  Bumpons are cheaper, but provide less clearance.
  Deleting anything else from this page may result in your EVM submission being rejected (until you add them back).
  Update the Label Text in the Label Table as needed for each Assembly Variant.
  You should delete this note too.
- 001
- 002
- ChangeMe!

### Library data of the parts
!PCB1 = PCB: Manufacturer: Any; PartNumber: TIDA-01598; SymbolCreator: a0412235
FID1-FID3 = Fiducial: Fiducial mark.  There is nothing to buy or mount.; SymbolCreator: codlsc
H1-H4 H9 H11 = NY PMS 440 0025 PH: Machine Screw, Round, #4-40 x 1/4, Nylon, Philips panhead; Manufacturer: B&F Fastener Supply; CompType: Hardware; SymbolCreator: codlsc; U/M: EA
H5-H8 H10 H12 = 1902C: Standoff, Hex, 0.5"L #4-40 Nylon; Manufacturer: Keystone; CompType: Hardware
LBL1 = THT-14-423-10: Thermal Transfer Printable Labels, 0.650" W x 0.200" H - 10,000 per roll; Manufacturer: Brady; SymbolCreator: a0412235; CompType: Label; Green_Lifecycle: Not Set; Green_REACh: Incomplete
Logo1 = TI_Logo: Texas Instrument Corporate Signature; SymbolCreator: a0412235
Logo2 = Pb-Free: SymbolCreator: a0412235
Logo3 = FCC_disclaimer: SymbolCreator: a0412235
ZZ1 = AssemblyNoteLabel: SymbolCreator: a0412235
ZZ2-ZZ4 = AssemblyNote: This Assembly Note will show in the PcbDoc and associated outputs; SymbolCreator: codlsc

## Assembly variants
001: not fitted R6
